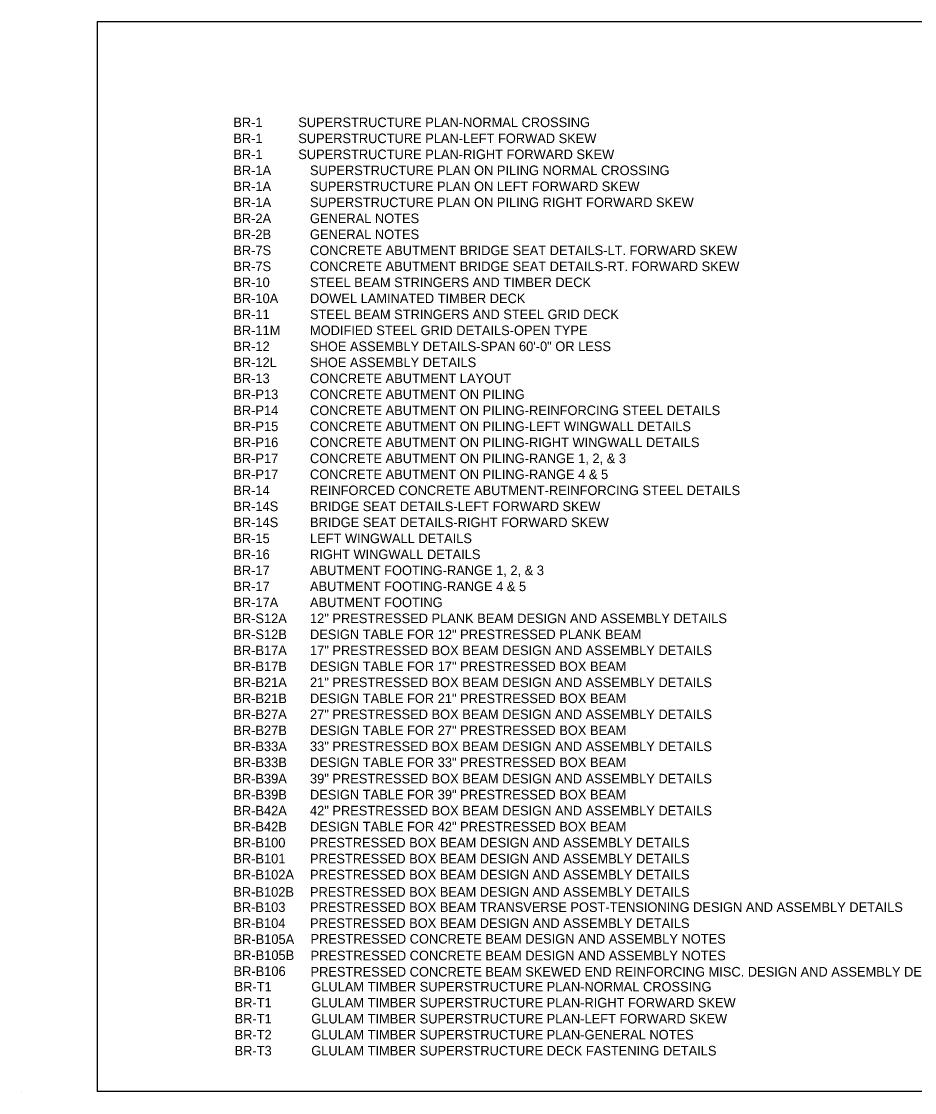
# Model space of a CAD drawing. Extents: x 3383 to 3913, y -1011 to -674.
# Drawn here: x 3383.5 to 3662.6, y -1010.5 to -675.8 of the extents above; entities that cross this region are included whole.
import ezdxf

# ---------------------------------------------------------------- set-up
doc = ezdxf.new("R2010")
doc.units = 0
for name, color, linetype in [('14', 7, 'Continuous'), ('63', 7, 'Continuous'), ('text', 7, 'Continuous')]:
    doc.layers.add(name, color=color, linetype=linetype)

msp = doc.modelspace()

# ---------------------------------------------------------------- linework, layer by layer
at = {"layer": '14'}
for p, q in [((3407.12, -675.81), (3407.09, -1010.22)), ((3407.12, -675.81), (3911.13, -675.83)), ((3911.13, -1010.23), (3407.09, -1010.22))]:
    msp.add_line(p, q, dxfattribs=at)
at = {"layer": '63'}
msp.add_line((3383.45, -1010.55), (3383.45, -1010.55), dxfattribs=at)

# ---------------------------------------------------------------- texts
at = {"layer": 'text'}
for s, height, p in [('BR-1          SUPERSTRUCTURE PLAN-NORMAL CROSSING', 3.0011, (3449.69, -708.85)), ('BR-1          SUPERSTRUCTURE PLAN-LEFT FORWAD SKEW', 3.0011, (3449.69, -713.85)), ('BR-1          SUPERSTRUCTURE PLAN-RIGHT FORWARD SKEW', 3.0011, (3449.69, -718.85)), ('BR-1A    ', 3.001, (3449.69, -723.85)), ('SUPERSTRUCTURE PLAN ON PILING NORMAL CROSSING', 3.0011, (3473.65, -723.85)), ('BR-1A', 3.001, (3449.69, -728.85)), ('SUPERSTRUCTURE PLAN ON LEFT FORWARD SKEW', 3.0011, (3473.65, -728.85)), ('BR-1A', 3.001, (3449.69, -733.85)), ('SUPERSTRUCTURE PLAN ON PILING RIGHT FORWARD SKEW', 3.0011, (3473.65, -733.85)), ('BR-2A', 3.001, (3449.69, -738.85)), ('GENERAL NOTES', 3.0011, (3473.65, -738.85)), ('BR-2B', 3.001, (3449.69, -743.85)), ('GENERAL NOTES', 3.0011, (3473.65, -743.85)), ('BR-7S', 3.001, (3449.69, -748.85)), ('CONCRETE ABUTMENT BRIDGE SEAT DETAILS-LT. FORWARD SKEW', 3.0011, (3473.65, -748.85)), ('BR-7S', 3.001, (3449.69, -753.85)), ('CONCRETE ABUTMENT BRIDGE SEAT DETAILS-RT. FORWARD SKEW', 3.0011, (3473.65, -753.85)), ('BR-10', 3.001, (3449.69, -758.85)), ('STEEL BEAM STRINGERS AND TIMBER DECK', 3.0011, (3473.65, -758.85)), ('BR-10A', 3.001, (3449.69, -763.85)), ('DOWEL LAMINATED TIMBER DECK', 3.0011, (3473.65, -763.85)), ('BR-11', 3.001, (3449.69, -768.85)), ('STEEL BEAM STRINGERS AND STEEL GRID DECK', 3.0011, (3473.65, -768.85)), ('BR-11M', 3.001, (3449.69, -773.85)), ('MODIFIED STEEL GRID DETAILS-OPEN TYPE', 3.0011, (3473.65, -773.85)), ('BR-12', 3.001, (3449.69, -778.85)), ('SHOE ASSEMBLY DETAILS-SPAN 60\'-0" OR LESS', 3.0011, (3473.65, -778.85)), ('BR-12L', 3.001, (3449.69, -783.85)), ('SHOE ASSEMBLY DETAILS', 3.0011, (3473.65, -783.85)), ('BR-13', 3.001, (3449.69, -788.85)), ('CONCRETE ABUTMENT LAYOUT', 3.0011, (3473.65, -788.85)), ('BR-P13', 3.001, (3449.69, -793.85)), ('CONCRETE ABUTMENT ON PILING', 3.0011, (3473.65, -793.85)), ('BR-P14', 3.001, (3449.69, -798.85)), ('CONCRETE ABUTMENT ON PILING-REINFORCING STEEL DETAILS', 3.0011, (3473.65, -798.85)), ('BR-P15', 3.001, (3449.69, -803.85)), ('CONCRETE ABUTMENT ON PILING-LEFT WINGWALL DETAILS', 3.0011, (3473.65, -803.85)), ('BR-P16', 3.001, (3449.69, -808.85)), ('CONCRETE ABUTMENT ON PILING-RIGHT WINGWALL DETAILS', 3.0011, (3473.65, -808.85)), ('BR-P17', 3.001, (3449.69, -813.85)), ('CONCRETE ABUTMENT ON PILING-RANGE 1, 2, & 3', 3.0011, (3473.65, -813.85)), ('BR-P17', 3.001, (3449.69, -818.85)), ('CONCRETE ABUTMENT ON PILING-RANGE 4 & 5', 3.0011, (3473.65, -818.85)), ('BR-14', 3.001, (3449.69, -823.85)), ('REINFORCED CONCRETE ABUTMENT-REINFORCING STEEL DETAILS', 3.0011, (3473.65, -823.85)), ('BR-14S', 3.001, (3449.69, -828.85)), ('BRIDGE SEAT DETAILS-LEFT FORWARD SKEW', 3.0011, (3473.65, -828.85)), ('BR-14S', 3.001, (3449.69, -833.85)), ('BRIDGE SEAT DETAILS-RIGHT FORWARD SKEW', 3.0011, (3473.65, -833.85)), ('BR-15', 3.001, (3449.69, -838.85)), ('LEFT WINGWALL DETAILS', 3.0011, (3473.65, -838.85)), ('BR-16', 3.001, (3449.69, -843.85)), ('RIGHT WINGWALL DETAILS', 3.0011, (3473.65, -843.85)), ('BR-17', 3.001, (3449.69, -848.85)), ('ABUTMENT FOOTING-RANGE 1, 2, & 3', 3.0011, (3473.65, -848.85)), ('BR-17', 3.001, (3449.69, -853.85)), ('ABUTMENT FOOTING-RANGE 4 & 5', 3.0011, (3473.65, -853.85)), ('BR-17A', 3.001, (3449.69, -858.85)), ('ABUTMENT FOOTING', 3.0011, (3473.65, -858.85)), ('BR-S12A', 3.001, (3449.69, -863.85)), ('12" PRESTRESSED PLANK BEAM DESIGN AND ASSEMBLY DETAILS', 3.0011, (3473.65, -863.85)), ('BR-S12B', 3.001, (3449.69, -868.85)), ('DESIGN TABLE FOR 12" PRESTRESSED PLANK BEAM', 3.0011, (3473.65, -868.85)), ('BR-B17A', 3.001, (3449.69, -873.85)), ('17" PRESTRESSED BOX BEAM DESIGN AND ASSEMBLY DETAILS', 3.0011, (3473.65, -873.85)), ('BR-B17B', 3.001, (3449.69, -878.85)), ('DESIGN TABLE FOR 17" PRESTRESSED BOX BEAM', 3.0011, (3473.65, -878.85)), ('BR-B21A', 3.001, (3449.69, -883.85)), ('21" PRESTRESSED BOX BEAM DESIGN AND ASSEMBLY DETAILS', 3.0011, (3473.65, -883.85)), ('BR-B21B', 3.001, (3449.69, -888.85)), ('DESIGN TABLE FOR 21" PRESTRESSED BOX BEAM', 3.0011, (3473.65, -888.85)), ('BR-B27A', 3.001, (3449.69, -893.85)), ('27" PRESTRESSED BOX BEAM DESIGN AND ASSEMBLY DETAILS', 3.0011, (3473.65, -893.85)), ('BR-B27B', 3.001, (3449.69, -898.85)), ('DESIGN TABLE FOR 27" PRESTRESSED BOX BEAM', 3.0011, (3473.65, -898.85)), ('BR-B33A', 3.001, (3449.69, -903.85)), ('33" PRESTRESSED BOX BEAM DESIGN AND ASSEMBLY DETAILS', 3.0011, (3473.65, -903.85)), ('BR-B33B', 3.001, (3449.69, -908.85)), ('DESIGN TABLE FOR 33" PRESTRESSED BOX BEAM', 3.0011, (3473.65, -908.85)), ('BR-B39A', 3.001, (3449.69, -913.94)), ('39" PRESTRESSED BOX BEAM DESIGN AND ASSEMBLY DETAILS', 3.0011, (3473.65, -913.94)), ('BR-B39B', 3.001, (3449.69, -918.94)), ('DESIGN TABLE FOR 39" PRESTRESSED BOX BEAM', 3.0011, (3473.65, -918.94)), ('BR-B42A', 3.001, (3449.69, -923.94)), ('42" PRESTRESSED BOX BEAM DESIGN AND ASSEMBLY DETAILS', 3.0011, (3473.65, -923.94)), ('BR-B42B', 3.001, (3449.69, -928.94)), ('DESIGN TABLE FOR 42" PRESTRESSED BOX BEAM', 3.0011, (3473.65, -928.94)), ('BR-B100', 3.001, (3449.69, -933.94)), ('PRESTRESSED BOX BEAM DESIGN AND ASSEMBLY DETAILS', 3.0011, (3473.65, -933.94)), ('BR-B101', 3.001, (3449.69, -938.94)), ('PRESTRESSED BOX BEAM DESIGN AND ASSEMBLY DETAILS', 3.0011, (3473.65, -938.94)), ('BR-B102A', 3.001, (3449.69, -943.94)), ('PRESTRESSED BOX BEAM DESIGN AND ASSEMBLY DETAILS', 3.0011, (3473.65, -943.94)), ('BR-B102B', 3.001, (3449.69, -949.34)), ('PRESTRESSED BOX BEAM DESIGN AND ASSEMBLY DETAILS', 3.0011, (3473.65, -949.34)), ('BR-B103', 3.001, (3449.69, -954.1)), ('PRESTRESSED BOX BEAM TRANSVERSE POST-TENSIONING DESIGN AND ASSEMBLY DETAILS', 3.0011, (3473.65, -954.1)), ('BR-B104', 3.001, (3449.69, -959.1)), ('PRESTRESSED BOX BEAM DESIGN AND ASSEMBLY DETAILS', 3.0011, (3473.65, -959.1)), ('BR-B105A', 3.001, (3449.76, -964.13)), ('PRESTRESSED CONCRETE BEAM DESIGN AND ASSEMBLY NOTES', 3.0011, (3473.82, -964)), ('BR-B105B', 3.001, (3449.76, -969.13)), ('PRESTRESSED CONCRETE BEAM DESIGN AND ASSEMBLY NOTES', 3.0011, (3473.82, -969.23)), ('BR-B106', 3.001, (3449.76, -974.13)), ('PRESTRESSED CONCRETE BEAM SKEWED END REINFORCING MISC. DESIGN AND ASSEMBLY DETAILS', 3.0011, (3473.82, -974.29)), ('BR-T1', 3.001, (3450.09, -978.96)), ('GLULAM TIMBER SUPERSTRUCTURE PLAN-NORMAL CROSSING', 3.0011, (3474.05, -978.96)), ('BR-T1', 3.001, (3450.09, -983.96)), ('GLULAM TIMBER SUPERSTRUCTURE PLAN-RIGHT FORWARD SKEW', 3.0011, (3474.05, -983.96)), ('BR-T1', 3.001, (3450.09, -988.96)), ('GLULAM TIMBER SUPERSTRUCTURE PLAN-LEFT FORWARD SKEW', 3.0011, (3474.05, -988.96)), ('BR-T2', 3.001, (3450.09, -993.96)), ('GLULAM TIMBER SUPERSTRUCTURE PLAN-GENERAL NOTES', 3.0011, (3474.05, -993.96)), ('BR-T3', 3.001, (3450.09, -998.96)), ('GLULAM TIMBER SUPERSTRUCTURE DECK FASTENING DETAILS', 3.0011, (3474.05, -998.96))]:
    msp.add_text(s, height=height, dxfattribs=at).set_placement(p)

doc.saveas('drawing.dxf')
